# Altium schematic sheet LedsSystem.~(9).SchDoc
size A4
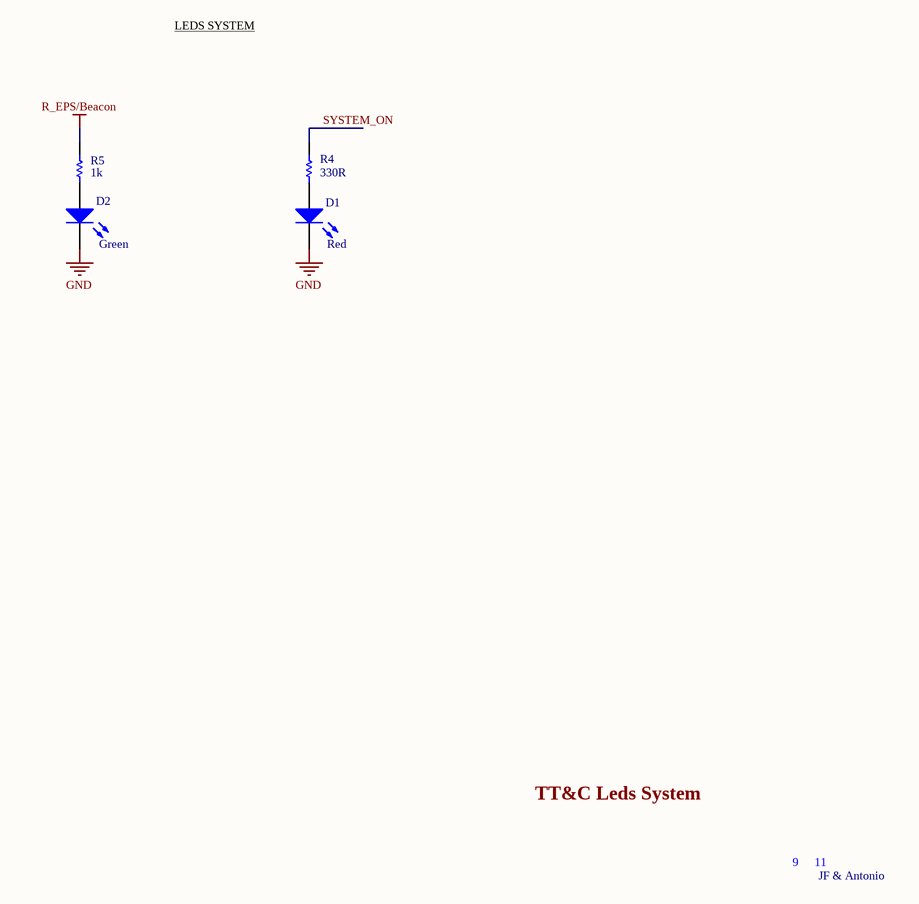
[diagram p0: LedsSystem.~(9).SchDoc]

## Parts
D1  Red  [LEDR]
D2  Green  [LEDG]
R4  value 330R  [R330]
R5  1k  [R1k]

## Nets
GND: D1.2(K) D2.2(K)
R_EPS/Beacon: R5.2
SYSTEM_ON: R4.2

Not connected (* = marked no-connect by the designer): D1 1(A); D2 1(A); R4 1; R5 1

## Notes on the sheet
- LEDS SYSTEM
- TT&C Leds System
- 9
- 11
- JF & Antonio

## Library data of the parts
D1 D2 = LED2: Typical RED, GREEN, YELLOW, AMBER GaAs LED
R4 R5 = Res1: Resistor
